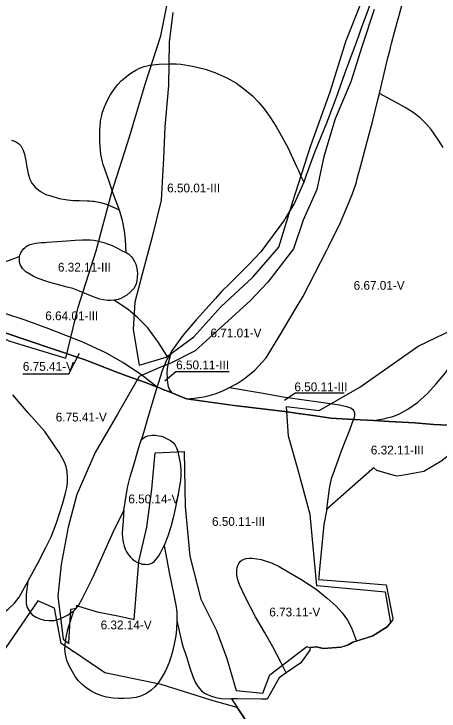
# Model space of a CAD drawing. Extents: x -555156 to -540209, y -1046851 to -1035695.
# Drawn here: x -542621 to -542138, y -1041348 to -1040556 of the extents above; entities that cross this region are included whole.
import ezdxf

# ---------------------------------------------------------------- set-up
doc = ezdxf.new("R2010")
doc.units = 0
for name, color, linetype in [('Vrstva 27', 7, 'Continuous'), ('Vrstva 28', 7, 'Continuous'), ('Vrstva 29', 7, 'Continuous')]:
    doc.layers.add(name, color=color, linetype=linetype)

msp = doc.modelspace()

# ---------------------------------------------------------------- linework, layer by layer
at = {"layer": 'Vrstva 27'}
for points in [[(-542611.25, -1040965.07), (-542559.26, -1040965.07), (-542546.9, -1040941.63)], [(-542450.16, -1040973.16), (-542437.38, -1040962.3), (-542376.86, -1040962.3)], [(-542313.91, -1040995.14), (-542301.93, -1040986.59), (-542246.14, -1040986.59)]]:
    msp.add_lwpolyline(points, dxfattribs=at)
at = {"layer": 'Vrstva 28'}
for points in [[(-542164.17, -1040281.3), (-542162.59, -1040313.22), (-542162.32, -1040318.6), (-542161.89, -1040327.35), (-542161.89, -1040350.2), (-542161.89, -1040353.44), (-542162.98, -1040375.05), (-542165.86, -1040395.45), (-542173.44, -1040425.26), (-542195.2, -1040485.09), (-542201.8, -1040503.71), (-542210.56, -1040528.46), (-542227.02, -1040573.44), (-542229.94, -1040581.38), (-542232.51, -1040588.39), (-542240.85, -1040611.09), (-542245.19, -1040622.89), (-542253.88, -1040646.81), (-542265.32, -1040678.33), (-542280.02, -1040713.71), (-542286.58, -1040732.12), (-542287.75, -1040735.39), (-542288.76, -1040738.22), (-542292.05, -1040747.44)], [(-542206.14, -1040646.59), (-542196.46, -1040606.05), (-542194.03, -1040596.4), (-542193.15, -1040592.91), (-542192.35, -1040589.71), (-542189.08, -1040576.69), (-542179.67, -1040543.74), (-542171.83, -1040521.51), (-542168.2, -1040511.01), (-542165.15, -1040502.22), (-542161.27, -1040491.46), (-542154.4, -1040476.07), (-542144.84, -1040455.59), (-542137.07, -1040440.65)], [(-542501.52, -1040779.15), (-542501.89, -1040778.19), (-542503.38, -1040774.3), (-542505.25, -1040769.44), (-542508.98, -1040759.12), (-542514.19, -1040744.16), (-542520.02, -1040727.27), (-542520.74, -1040724.06), (-542522.56, -1040715.91), (-542524.05, -1040701.98), (-542524.05, -1040688.38), (-542523.29, -1040679.28), (-542523.16, -1040677.77), (-542522.75, -1040675.92), (-542522.15, -1040673.19), (-542521.21, -1040668.95), (-542518.67, -1040661.78), (-542515.44, -1040654.77), (-542511.94, -1040648.54), (-542508.27, -1040642.56), (-542503.41, -1040636.24), (-542499.48, -1040632.06), (-542495.9, -1040629.07), (-542491.12, -1040625.22), (-542487.45, -1040622.49), (-542483.01, -1040619.84), (-542478.85, -1040617.77), (-542473.62, -1040615.98), (-542466.9, -1040614.49), (-542456.83, -1040613.35), (-542443.87, -1040612.77), (-542443.54, -1040612.75), (-542437.17, -1040612.99), (-542431.74, -1040613.2), (-542418.59, -1040615.29), (-542404.26, -1040619.03), (-542393.05, -1040622.76), (-542379.46, -1040628.59), (-542368.41, -1040634.87), (-542358.7, -1040642.19), (-542350.33, -1040649.36), (-542343.16, -1040656.69), (-542335.99, -1040665.5), (-542329.72, -1040674.32), (-542323, -1040684.63), (-542317.77, -1040694.2), (-542310, -1040707.75), (-542300.24, -1040729.33), (-542298.52, -1040733.13), (-542296.89, -1040736.73), (-542295.59, -1040739.6), (-542292.05, -1040747.44)], [(-542376.56, -1040980.79), (-542367.94, -1040976.09), (-542359.75, -1040970.8), (-542347.5, -1040960.94), (-542334.7, -1040946.82), (-542320.06, -1040922.76), (-542301.71, -1040892.1), (-542293.13, -1040877.78), (-542265.81, -1040824.74), (-542265.39, -1040823.93), (-542263.94, -1040820.97), (-542252.93, -1040798.52), (-542251.54, -1040795.68), (-542242.39, -1040774.23), (-542236.9, -1040761.42), (-542232.94, -1040749.55), (-542232.19, -1040747.3), (-542232.08, -1040746.89), (-542231.23, -1040743.58), (-542226.18, -1040724.02), (-542220.17, -1040701.27), (-542213.9, -1040678.77), (-542207.89, -1040653.84), (-542206.14, -1040646.59)], [(-542133.66, -1040708), (-542138.74, -1040699.7), (-542147.36, -1040687.41), (-542152.85, -1040680.87), (-542159.91, -1040674.07), (-542167.75, -1040668.06), (-542176.9, -1040662.56), (-542187.92, -1040656.54), (-542206.14, -1040646.59)], [(-542624.18, -1040699.4), (-542619.91, -1040700.94), (-542616.16, -1040703.41), (-542613.26, -1040706.4), (-542611.29, -1040710.16), (-542609.84, -1040714.17), (-542608.09, -1040722.65), (-542606.74, -1040730.14), (-542606.11, -1040733.72), (-542605.4, -1040737.74), (-542603.46, -1040743.87), (-542601.16, -1040748.29), (-542597.42, -1040752.92), (-542591.45, -1040758), (-542585.32, -1040761.29), (-542581.54, -1040762.39), (-542579.65, -1040762.94), (-542569.94, -1040765.78), (-542560.68, -1040767.27)], [(-542292.05, -1040747.44), (-542302.83, -1040771.85), (-542303.21, -1040772.48), (-542313.15, -1040788.67), (-542314.07, -1040790.16), (-542340.73, -1040826.51), (-542342.58, -1040828.42), (-542346.03, -1040831.98), (-542356.41, -1040842.71), (-542376.19, -1040862.32), (-542385.69, -1040871.74), (-542392.57, -1040879.45), (-542414.18, -1040903.65), (-542429.61, -1040921.43), (-542442.4, -1040939.21)], [(-542560.68, -1040767.27), (-542553.96, -1040768.02), (-542550.37, -1040768.02), (-542546.79, -1040768.02), (-542538.42, -1040768.47), (-542535.73, -1040768.63), (-542532.43, -1040768.83), (-542531.1, -1040768.91), (-542525.07, -1040769.94), (-542523.19, -1040770.26), (-542516.31, -1040772.35), (-542510.19, -1040774.89), (-542506.1, -1040776.9), (-542501.52, -1040779.15)], [(-542493.86, -1040827.2), (-542494.61, -1040813), (-542495.95, -1040802.69), (-542498.23, -1040790.81), (-542501.52, -1040779.15)], [(-542615.09, -1040831.94), (-542614.77, -1040830.41), (-542613.65, -1040827.78), (-542612.69, -1040825.9), (-542611.56, -1040824.34), (-542610.49, -1040823.12), (-542609.17, -1040821.85), (-542607.52, -1040820.48), (-542605.76, -1040819.41), (-542603.22, -1040818.09), (-542600.2, -1040817.21), (-542596.44, -1040816.53), (-542590.49, -1040815.89), (-542585.68, -1040815.69), (-542583.57, -1040815.6), (-542572.43, -1040814.71), (-542561.68, -1040813.86), (-542551.95, -1040813.35), (-542543.75, -1040813), (-542539.12, -1040812.88), (-542534.34, -1040812.98), (-542530.59, -1040813.27), (-542526.83, -1040813.86), (-542519.37, -1040815.86), (-542515.27, -1040817.47), (-542509.76, -1040819.37), (-542503.66, -1040822.25), (-542498.3, -1040825.18), (-542493.86, -1040827.2)], [(-542493.86, -1040827.2), (-542491.06, -1040829.28), (-542488.24, -1040831.67), (-542486.36, -1040833.97), (-542484.49, -1040837.3), (-542483.12, -1040840.46), (-542482.18, -1040843.88), (-542481.58, -1040847.55), (-542481.16, -1040851.56), (-542481.29, -1040854.68), (-542481.33, -1040855.75), (-542481.84, -1040859.59), (-542482.69, -1040862.92), (-542483.8, -1040865.31), (-542485.25, -1040867.96), (-542487.3, -1040870.52), (-542489.61, -1040872.83), (-542493.19, -1040875.73), (-542496.52, -1040877.78), (-542500.11, -1040879.4), (-542503.09, -1040880.52), (-542507.45, -1040881.45)], [(-542615.09, -1040831.94), (-542622.74, -1040834.63), (-542630.36, -1040837.32), (-542637.68, -1040840.31), (-542650.35, -1040845.79)], [(-542514.79, -1040881.63), (-542519.57, -1040881.11), (-542523.83, -1040880.09), (-542532.28, -1040877.27), (-542546.88, -1040871.04), (-542554.48, -1040868.17), (-542560.96, -1040866.47), (-542569.33, -1040864.25), (-542579.23, -1040861.6), (-542586.4, -1040859.38), (-542591.68, -1040857.72), (-542595.97, -1040855.91), (-542599.72, -1040854.11), (-542603.53, -1040851.96), (-542607.92, -1040849.03), (-542609.7, -1040847.4), (-542611.7, -1040845.35), (-542612.97, -1040843.69), (-542614.04, -1040841.69), (-542614.67, -1040839.88), (-542615.11, -1040837.88), (-542615.31, -1040835.73), (-542615.31, -1040833), (-542615.09, -1040831.94)], [(-542750.36, -1040868.71), (-542733.5, -1040876.07), (-542722.73, -1040880.77), (-542676.59, -1040898.5), (-542645.13, -1040914.12), (-542608.12, -1040926.61), (-542540.62, -1040949.39), (-542505.86, -1040963.01), (-542488.41, -1040969.43), (-542470.89, -1040975.38), (-542466.21, -1040977.19), (-542458.71, -1040980.09)], [(-542458.71, -1040980.09), (-542470.89, -1040975.38), (-542488.41, -1040969.43), (-542505.86, -1040963.01), (-542540.62, -1040949.39), (-542608.12, -1040926.61), (-542645.13, -1040914.12), (-542676.59, -1040898.5), (-542722.73, -1040880.77), (-542733.5, -1040876.07)], [(-542458.71, -1040980.09), (-542467.28, -1040973.4), (-542476.18, -1040966.45), (-542485.66, -1040960.23), (-542490.57, -1040957.01), (-542497.82, -1040952.26), (-542517.16, -1040941.28), (-542543.3, -1040929.09), (-542581.99, -1040913.92), (-542608.91, -1040903.99), (-542631.91, -1040896.4), (-542660.93, -1040888.03), (-542696.06, -1040876.83)], [(-542507.45, -1040881.45), (-542511.37, -1040881.8), (-542514.79, -1040881.63)], [(-542446.43, -1040947.11), (-542447.11, -1040945.91), (-542451.72, -1040937.86), (-542457.84, -1040928.44), (-542459.32, -1040926.44), (-542469.34, -1040912.9), (-542480.25, -1040901.84), (-542480.65, -1040901.5), (-542483.22, -1040899.31), (-542491.3, -1040892.42), (-542507.45, -1040881.45)], [(-542442.4, -1040939.21), (-542443.08, -1040941.72), (-542446.57, -1040954.67), (-542447.47, -1040959.6), (-542447.62, -1040964.09), (-542447.32, -1040970.21), (-542447.27, -1040971.05), (-542447.02, -1040975.44), (-542446.27, -1040979.48), (-542445.46, -1040981.46), (-542444.98, -1040982.62), (-542443.42, -1040984.87)], [(-542442.4, -1040939.21), (-542444.36, -1040943.05)], [(-542199.52, -1041015.7), (-542198.76, -1041015.5), (-542190.86, -1041013.46), (-542183.84, -1041011.07), (-542173.68, -1041005.24), (-542162.63, -1040997.77), (-542151.42, -1040987.45), (-542141.41, -1040976.41), (-542130.95, -1040963.86), (-542113.35, -1040938.19)], [(-542458.71, -1040980.09), (-542457.69, -1040976.94), (-542454.28, -1040966.41), (-542452.85, -1040961.97), (-542448.41, -1040950.98), (-542446.43, -1040947.11)], [(-542444.36, -1040943.05), (-542446.43, -1040947.11)], [(-542476.71, -1041040.42), (-542475.45, -1041036.75), (-542472.54, -1041027.9), (-542469.63, -1041016.88), (-542458.71, -1040980.09)], [(-542458.71, -1040980.09), (-542456, -1040981.14)], [(-542441.85, -1040986.82), (-542445.98, -1040985.16), (-542452.84, -1040982.41), (-542456, -1040981.14), (-542458.71, -1040980.09)], [(-542456, -1040981.14), (-542452.84, -1040982.41), (-542445.98, -1040985.16), (-542425.31, -1040993.45), (-542370.83, -1041001.09), (-542364.87, -1041001.93), (-542310.6, -1041008.32), (-542300.92, -1041009.73), (-542281.49, -1041012.56), (-542261.4, -1041015.48), (-542235.46, -1041016.89)], [(-542425.31, -1040993.45), (-542416.42, -1040992.83), (-542408.23, -1040991.81), (-542406.21, -1040991.35), (-542400.8, -1040990.1), (-542392.95, -1040987.79), (-542384.16, -1040984.38), (-542376.56, -1040980.79)], [(-542376.56, -1040980.79), (-542338.33, -1040987.1), (-542315.59, -1040991.28), (-542251.62, -1041000.36), (-542243.42, -1041002.15), (-542238.81, -1041003.78), (-542238.63, -1041003.9), (-542236.51, -1041005.23), (-542235.06, -1041007.28), (-542234.29, -1041009.5), (-542234.29, -1041012.15), (-542234.42, -1041012.79), (-542234.72, -1041014.28)], [(-542605.62, -1041201.21), (-542594.17, -1041180.43), (-542585.06, -1041162.62), (-542579.34, -1041150.32), (-542573.19, -1041134.63), (-542566.4, -1041113.29), (-542562.77, -1041100.69), (-542561.19, -1041094.75), (-542560.47, -1041089.06), (-542560.47, -1041083.12), (-542561.07, -1041076.09), (-542562.16, -1041070.52), (-542563.86, -1041065.67), (-542566.52, -1041060.71), (-542570.22, -1041054.46), (-542586.32, -1041030.72), (-542605.19, -1041009.3), (-542622.63, -1040988.87)], [(-542443.42, -1040984.87), (-542441.85, -1040986.82)], [(-542425.31, -1040993.45), (-542441.85, -1040986.82)], [(-541711.53, -1040984.07), (-541720.74, -1040984.11), (-541753.03, -1040984.57), (-541788.51, -1040985.92), (-541829.15, -1040987.85), (-541883.28, -1040998.82), (-541905.62, -1041003.69), (-541926.36, -1041008.21), (-541989.22, -1041017.54), (-542012.92, -1041021.23), (-542038.14, -1041023.7), (-542055.32, -1041025.28), (-542092.44, -1041025.28), (-542136.24, -1041023.22), (-542144.14, -1041022.56), (-542165.98, -1041020.75), (-542194.83, -1041019.46), (-542212.55, -1041018.13)], [(-542235.46, -1041016.89), (-542261.4, -1041015.48), (-542281.49, -1041012.56), (-542300.92, -1041009.73), (-542310.6, -1041008.32), (-542364.87, -1041001.93), (-542371.83, -1041000.95), (-542425.31, -1040993.45)], [(-542265.94, -1041119.1), (-542262.86, -1041095.27), (-542260.56, -1041084.25), (-542256.8, -1041073.95), (-542252.56, -1041062.07), (-542249.05, -1041052.62), (-542244.09, -1041040.02), (-542239.6, -1041028.87), (-542235.46, -1041016.89)], [(-542234.72, -1041014.28), (-542235.46, -1041016.89)], [(-542235.46, -1041016.89), (-542212.55, -1041018.13)], [(-542212.55, -1041018.13), (-542235.46, -1041016.89)], [(-542212.55, -1041018.13), (-542199.52, -1041015.7)], [(-542212.55, -1041018.13), (-542194.83, -1041019.46), (-542165.98, -1041020.75), (-542144.14, -1041022.56), (-542136.24, -1041023.22), (-542092.44, -1041025.28), (-542055.32, -1041025.28)], [(-542055.32, -1041025.28), (-542092.96, -1041033.89), (-542115.94, -1041048.5), (-542135.22, -1041064.11), (-542155.58, -1041076.19), (-542180.4, -1041080.49), (-542186.41, -1041081.53), (-542189.29, -1041080.7), (-542208.88, -1041075.04), (-542212.45, -1041072.13), (-542214.58, -1041074), (-542265.94, -1041119.1)], [(-542476.71, -1041040.42), (-542475.34, -1041038.82), (-542473.45, -1041037.32), (-542471.63, -1041036.37), (-542469.45, -1041035.62), (-542466.64, -1041035.15), (-542463.81, -1041034.94), (-542460.69, -1041035.01)], [(-542460.69, -1041035.01), (-542457.3, -1041035.5), (-542453.91, -1041036.12), (-542450.73, -1041037.16), (-542447.2, -1041038.82), (-542443.6, -1041040.83), (-542440.21, -1041043.46), (-542438.13, -1041046.37), (-542436.75, -1041049.07), (-542435.38, -1041053.31), (-542433.93, -1041059.37), (-542432.47, -1041066.28), (-542431.75, -1041074.27), (-542431.87, -1041080.7), (-542432.19, -1041086.37), (-542434.97, -1041101.64), (-542438.36, -1041118.6), (-542440.66, -1041128.78), (-542443.08, -1041138.84), (-542446.48, -1041149.74), (-542450.83, -1041160.24)], [(-542496.58, -1041120.37), (-542492.24, -1041094.27), (-542489.21, -1041082.27), (-542484.98, -1041067.25), (-542480.62, -1041052.58), (-542477.87, -1041043.78), (-542476.71, -1041040.42)], [(-542553.39, -1041234.34), (-542551.08, -1041232.04), (-542548.12, -1041228.43), (-542544, -1041220.92), (-542531.53, -1041195.96), (-542508.52, -1041144.95), (-542496.58, -1041120.37)], [(-542496.79, -1041124.48), (-542497.48, -1041132.45), (-542498.11, -1041140.75), (-542498.3, -1041146.57), (-542498.09, -1041151.21), (-542497.4, -1041156.33), (-542496.15, -1041161.04), (-542494.9, -1041164.37), (-542493.52, -1041167.55), (-542491.38, -1041170.67), (-542489.09, -1041173.51), (-542486.67, -1041175.79), (-542483.56, -1041178.15), (-542480.99, -1041179.39), (-542478.5, -1041180.36), (-542475.6, -1041181.26), (-542471.86, -1041181.61), (-542469.71, -1041181.68), (-542466.81, -1041181.12), (-542463.83, -1041179.74), (-542461.55, -1041178.01), (-542459.26, -1041175.44), (-542456.77, -1041171.84), (-542454.84, -1041168.52), (-542453.38, -1041165.61), (-542450.83, -1041160.24)], [(-542496.58, -1041120.37), (-542496.79, -1041124.48)], [(-542265.94, -1041119.1), (-542269.33, -1041136.17), (-542273.78, -1041183.17), (-542274.11, -1041186.62), (-542275.04, -1041196.43), (-542275.26, -1041198.78), (-542226.2, -1041202.71), (-542198.3, -1041204.95), (-542190.71, -1041243.27), (-542191.29, -1041245.2), (-542197.18, -1041252.73), (-542213.7, -1041263.03), (-542232.09, -1041268.86)], [(-542450.83, -1041160.24), (-542444.9, -1041190.78), (-542440.02, -1041214.74), (-542437.5, -1041227.98), (-542436.28, -1041235.73), (-542436.28, -1041245.31)], [(-542312.19, -1041305.07), (-542318.13, -1041292.92), (-542327.24, -1041275.32), (-542336.56, -1041258.57), (-542346.95, -1041241.18), (-542357.76, -1041220.19), (-542364.75, -1041205.56), (-542366.09, -1041201.43), (-542367.2, -1041197.56), (-542368.03, -1041193.82), (-542368.23, -1041190.7), (-542368.1, -1041188.14), (-542367.82, -1041185.3), (-542366.99, -1041182.95), (-542365.95, -1041180.8), (-542364.5, -1041178.51), (-542362.49, -1041176.92), (-542360.41, -1041176.02), (-542357.78, -1041175.12), (-542354.12, -1041174.64), (-542350.52, -1041174.5), (-542345.4, -1041175.19)], [(-542345.4, -1041175.19), (-542340.41, -1041176.16), (-542334.81, -1041177.89), (-542328.86, -1041180.04), (-542320, -1041184.05), (-542309.9, -1041190.01), (-542295.43, -1041198.52), (-542278.04, -1041209.74), (-542265.45, -1041220.04), (-542255.28, -1041229.01), (-542248.36, -1041236.69), (-542242.42, -1041245.17), (-542237.82, -1041253.89), (-542232.09, -1041268.86)], [(-542788.89, -1041238.38), (-542782.63, -1041243.39), (-542776.22, -1041247.02), (-542766.89, -1041250.78), (-542758.29, -1041252.96), (-542745.79, -1041253.66), (-542726.08, -1041254.5), (-542706.37, -1041254.08), (-542683.05, -1041252.17), (-542667.16, -1041249.63), (-542653.81, -1041246.45), (-542644.69, -1041243.26), (-542636, -1041238.39), (-542628.59, -1041233.09), (-542620.74, -1041225.88), (-542615.37, -1041218.81), (-542605.62, -1041201.21)], [(-542605.62, -1041201.21), (-542607.61, -1041215.44), (-542607.76, -1041221.38), (-542607.52, -1041226.59), (-542606.43, -1041230.59), (-542604.37, -1041234.58), (-542600.86, -1041238.83), (-542596.38, -1041241.61), (-542592.02, -1041243.43), (-542587.3, -1041245.13), (-542581.72, -1041245.61), (-542575.91, -1041245.37), (-542570.58, -1041243.91), (-542565.74, -1041241.98), (-542560.65, -1041239.43), (-542557.14, -1041237.13), (-542553.39, -1041234.34)], [(-542436.28, -1041245.31), (-542436.77, -1041255.61), (-542437.5, -1041262.88), (-542439.25, -1041272.42), (-542441.55, -1041282.23), (-542445.06, -1041293.26), (-542449.06, -1041302.59), (-542453.42, -1041309.98), (-542457.05, -1041315.8), (-542461.29, -1041321.01), (-542465.65, -1041324.76), (-542470.74, -1041328.28), (-542476.31, -1041331.07), (-542482.73, -1041332.88), (-542489.15, -1041333.73), (-542496.29, -1041334.22), (-542502.59, -1041334.22), (-542508.77, -1041333.73), (-542516.15, -1041332.76), (-542521.6, -1041331.19), (-542527.66, -1041328.64), (-542532.87, -1041326.22), (-542538.44, -1041322.83), (-542544.01, -1041318.34), (-542548.13, -1041314.1), (-542552, -1041309.13), (-542555.27, -1041303.2), (-542558.18, -1041297.86), (-542561.21, -1041290.84), (-542562.9, -1041283.81), (-542563.49, -1041278.05), (-542563.07, -1041269.15), (-542561.58, -1041262.57), (-542559.68, -1041254.09), (-542553.39, -1041234.34)], [(-542436.28, -1041245.31), (-542430.09, -1041272.37), (-542425.12, -1041287.76), (-542421.73, -1041299.27), (-542418.1, -1041308.96), (-542415.43, -1041315.39), (-542412.28, -1041320.6), (-542408.41, -1041325.2), (-542404.77, -1041327.87), (-542400.78, -1041330.05), (-542396.78, -1041331.62), (-542391.82, -1041333.08), (-542386.12, -1041334.05), (-542374.33, -1041334.47)], [(-542232.09, -1041268.86), (-542236.18, -1041270.16), (-542242.64, -1041273.68), (-542249.01, -1041275.7), (-542269.97, -1041277.3), (-542277.64, -1041275.35), (-542284.6, -1041276.02), (-542285.23, -1041279.09), (-542295.33, -1041293.52), (-542312.19, -1041305.07)], [(-542312.19, -1041305.07), (-542320.17, -1041310.54), (-542333.5, -1041335), (-542340.44, -1041334.91), (-542367.67, -1041334.56), (-542374.33, -1041334.47)], [(-542374.33, -1041334.47), (-542345.88, -1041377.29), (-542319.7, -1041412.45), (-542323.13, -1041412.45), (-542321.53, -1041414.69), (-542314.85, -1041424.04), (-542313.06, -1041426.54)]]:
    msp.add_lwpolyline(points, dxfattribs=at)
at = {"layer": 'Vrstva 29'}
for points in [[(-542440.84491, -1040554.632019), (-542444.956909, -1040588.317017), (-542445.97699, -1040637.505981), (-542450.062012, -1040684.317017), (-542451.390991, -1040719.934021), (-542454.041992, -1040767.667908), (-542464.481995, -1040809.44397), (-542475.763, -1040851.895996), (-542484.091003, -1040883.684998), (-542485.934998, -1040914.64801), (-542479.112, -1040955.23999), (-542448.447021, -1040946.062988), (-542417.052002, -1040923.171997), (-542386.46698, -1040888.953979), (-542349.815979, -1040855.395996), (-542320.494995, -1040821.039978), (-542304.375977, -1040769.40802), (-542284.237976, -1040706.71991), (-542261.880981, -1040644.784973), (-542243.72699, -1040586.223022), (-542212.925903, -1040507.836975)], [(-542859.281638, -1040909.543894), (-542858.57, -1040908.57), (-542857.747526, -1040908.857424), (-542764.611991, -1040867.182004), (-542714.161992, -1040894.643997), (-542664.604006, -1040911.536003), (-542625.996009, -1040928.001997), (-542562.621009, -1040947.166002), (-542548.649, -1040889.425993), (-542527.839996, -1040825.278004), (-542510.349005, -1040758.724995), (-542490.184002, -1040695.784996), (-542472.397994, -1040635.904997), (-542454.404994, -1040581.157999), (-542445.100004, -1040533.381993)], [(-542212.020995, -1040551.105008), (-542225.747, -1040592.523004), (-542238.631995, -1040633.268008), (-542256.257997, -1040675.283), (-542269.391003, -1040718.299008), (-542277.032999, -1040755.527), (-542292.624994, -1040790.612994), (-542303.616997, -1040822.908993), (-542333.023997, -1040860.915002), (-542352.627995, -1040881.758008), (-542390.610999, -1040916.086006), (-542415.446999, -1040938.928999), (-542443.294999, -1040953.090005), (-542455.548002, -1040957.994002), (-542478.972998, -1040968.027002), (-542503.869007, -1041011.038995), (-542529.066, -1041054.627005), (-542549.896002, -1041102.442003), (-542559.697991, -1041139.223004), (-542567.772005, -1041181.864001), (-542571.710995, -1041217.963003), (-542565.517006, -1041266.659994), (-542558.63184, -1041271.459921), (-542558.92, -1041270.77), (-542556.91, -1041232.59), (-542550.56, -1041231.33), (-542550.13, -1041228.11), (-542547.93, -1041229.09), (-542526.92, -1041235.63), (-542501.61, -1041240.47), (-542484.653134, -1041244.281682), (-542479.682994, -1041178.430999), (-542470.556999, -1041139.320993), (-542464.583007, -1041096.291999), (-542461.103994, -1041055.034009), (-542427.923995, -1041053.284003), (-542426.810992, -1041115.731994), (-542421.470999, -1041172.255006), (-542408.930992, -1041221.387993), (-542391.310994, -1041256.769004), (-542379.453005, -1041288.713992), (-542368.821001, -1041324.866997), (-542338.718997, -1041327.889993), (-542330.593006, -1041307.318005), (-542288.437993, -1041274.869995), (-542284.697229, -1041276.493797), (-542284.6, -1041276.02), (-542277.64, -1041275.35), (-542269.97, -1041277.3), (-542249.918704, -1041275.769367), (-542240.780442, -1041272.666742), (-542236.18, -1041270.16), (-542213.7, -1041263.03), (-542197.18, -1041252.73), (-542193.205924, -1041247.64939), (-542199.122996, -1041213.330998), (-542277.351998, -1041206.086999), (-542284.625007, -1041125.088005), (-542298.542993, -1041074.526995), (-542309.404994, -1041035.795001), (-542311.609009, -1041002.091996), (-542274.514002, -1041006.642993), (-542228.162999, -1040980.271993), (-542162.203006, -1040933.559002), (-542121.732003, -1040914.210991)], [(-542345.88, -1041377.29), (-542367.660512, -1041344.508223), (-542394.932983, -1041336.838013), (-542454.263977, -1041318.11499), (-542518.365906, -1041305.021973), (-542553.908476, -1041280.808173), (-542554.76, -1041280.73), (-542555.053022, -1041280.028437), (-542567.642029, -1041271.452026), (-542575.473022, -1041231.346985), (-542594.271912, -1041223.169006), (-542631.637024, -1041277.340027), (-542680.179016, -1041356.603027), (-542756.71991, -1041324.510986), (-542823.747986, -1041303.672913), (-542860.137024, -1041287.958984), (-542872.159973, -1041351.276001)]]:
    msp.add_lwpolyline(points, dxfattribs=at)

# ---------------------------------------------------------------- texts
at = {"layer": 'Vrstva 27'}
for s, p in [('6.50.01-III', (-542447.376548, -1040758.9)), ('6.32.11-III', (-542571.516548, -1040848.91)), ('6.67.01-V', (-542235.361006, -1040869.57)), ('6.64.01-III', (-542585.886548, -1040904.15)), ('6.71.01-V', (-542398.111006, -1040923.67)), ('6.50.11-III', (-542437.116548, -1040960.01)), ('6.75.41-V', (-542611.351006, -1040961.66)), ('6.50.11-III', (-542302.696548, -1040984.94)), ('6.75.41-V', (-542573.960288, -1041019.29)), ('6.32.11-III', (-542215.816548, -1041056.75)), ('6.50.14-V', (-542491.490884, -1041112.3)), ('6.50.11-III', (-542396.383926, -1041137.93)), ('6.73.11-V', (-542331.261006, -1041240.84)), ('6.32.14-V', (-542522.940884, -1041255.51))]:
    msp.add_text(s, height=10, dxfattribs=at).set_placement(p)

doc.saveas('drawing.dxf')
